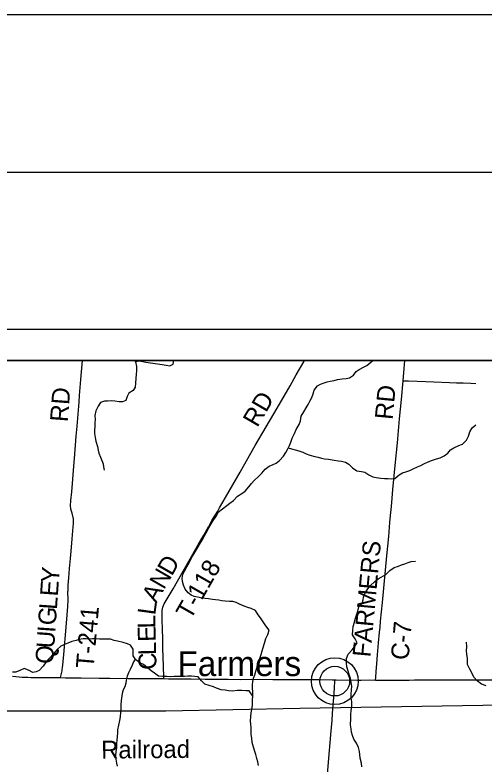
# Model space of a CAD drawing. Extents: x 0 to 48.6, y 0 to 22.
# Drawn here: x 4.141 to 5.632, y 19.616 to 22 of the extents above; entities that cross this region are included whole.
import ezdxf

# ---------------------------------------------------------------- set-up
doc = ezdxf.new("R2010")
doc.units = 0
for name, color, linetype in [('GM_X_Corporation', 7, 'Continuous'), ('GM_X_County_Road', 7, 'Continuous'), ('GM_X_County_Road_Text', 7, 'Continuous'), ('GM_X_Minor_River', 7, 'Continuous'), ('GM_X_Rail_Line', 7, 'Continuous'), ('GM_X_Rail_Line_Text', 7, 'Continuous'), ('GM_X_State_Route', 7, 'Continuous'), ('GM_X_Township_Road', 7, 'Continuous'), ('GM_X_Township_Road_Text', 7, 'Continuous'), ('GM_X_Unincorporated', 7, 'Continuous'), ('GM_X_Unincorporated_Location', 7, 'Continuous'), ('GM_X_Unincorporated_Text', 7, 'Continuous'), ('SH_Border', 7, 'Continuous'), ('SH_Cut_Line', 7, 'Continuous'), ('SH_Data', 7, 'Continuous')]:
    doc.layers.add(name, color=color, linetype=linetype)

msp = doc.modelspace()

# ---------------------------------------------------------------- linework, layer by layer
at = {"layer": 'GM_X_Corporation'}
for points in [[(8.9, 20.9), (2.1, 20.9), (2.1, 14.1)], [(5.5264, 17.0064), (5.8387, 17.2541), (6.5365, 17.7727), (6.4996, 17.9212), (6.3396, 18.6531), (6.2759, 18.9159), (6.0412, 19.8859), (5.8236, 20.7829), (5.795, 20.9), (2.1, 20.9), (2.1, 14.1)]]:
    msp.add_lwpolyline(points, dxfattribs=at)
at = {"layer": 'GM_X_County_Road'}
for points in [[(5.3742, 20.8361), (5.3776, 20.8749), (5.3801, 20.9)], [(5.2869, 19.8833), (5.2875, 19.8913), (5.2888, 19.9111), (5.2908, 19.9346), (5.2935, 19.9637), (5.2966, 20.0015), (5.2998, 20.0361), (5.301, 20.051), (5.3026, 20.0708), (5.3084, 20.1301), (5.3227, 20.2792), (5.3286, 20.3398), (5.3324, 20.385), (5.3344, 20.4073), (5.3372, 20.4357), (5.3397, 20.4623), (5.3422, 20.4895), (5.3494, 20.5662), (5.3562, 20.6386), (5.3597, 20.677), (5.3633, 20.7147), (5.3689, 20.7765), (5.3742, 20.8361)], [(5.1109, 19.3182), (5.1158, 19.3783), (5.1186, 19.4104), (5.1221, 19.4507), (5.1248, 19.4835), (5.1272, 19.5081), (5.1285, 19.523), (5.1315, 19.5583), (5.1373, 19.6214), (5.1395, 19.648), (5.143, 19.6839), (5.1452, 19.7105), (5.1471, 19.7328), (5.149, 19.755), (5.1505, 19.7774), (5.1525, 19.8046), (5.1548, 19.84), (5.1559, 19.8623), (5.1569, 19.8771), (5.1574, 19.8844)], [(5.1574, 19.8844), (5.1621, 19.8843), (5.2292, 19.8835), (5.241, 19.8835), (5.2665, 19.8836), (5.2869, 19.8833)]]:
    msp.add_lwpolyline(points, dxfattribs=at)
at = {"layer": 'GM_X_Minor_River'}
for points in [[(4.5209, 20.9), (4.5241, 20.8966), (4.5273, 20.881), (4.5267, 20.8685), (4.5254, 20.8559), (4.5245, 20.8442), (4.5239, 20.8286), (4.5226, 20.8154), (4.5164, 20.8052), (4.503, 20.7963), (4.4975, 20.7853), (4.4932, 20.7729), (4.4829, 20.7684), (4.4722, 20.7686), (4.4578, 20.7707), (4.4483, 20.7719), (4.435, 20.7713), (4.4252, 20.7711), (4.4122, 20.7663), (4.4048, 20.755), (4.3974, 20.7399), (4.3949, 20.7252), (4.3951, 20.7122), (4.395, 20.7024), (4.3945, 20.6914), (4.3935, 20.6781), (4.3938, 20.6679), (4.3955, 20.6557), (4.3976, 20.6435), (4.4031, 20.6264), (4.4052, 20.6149), (4.4077, 20.605), (4.4121, 20.5928), (4.4169, 20.5825), (4.4206, 20.5711), (4.4224, 20.5616), (4.4241, 20.5517)], [(4.5242, 20.8959), (4.5332, 20.8995), (4.5473, 20.8974), (4.5571, 20.8954), (4.5719, 20.8933), (4.5939, 20.89), (4.6087, 20.8879), (4.6212, 20.8858), (4.6329, 20.8838), (4.644, 20.889), (4.6455, 20.9)], [(5.1233, 20.8292), (5.1332, 20.8329), (5.1428, 20.835), (5.1549, 20.8368), (5.1664, 20.8397), (5.1805, 20.8425), (5.1938, 20.8431), (5.2044, 20.8456), (5.2171, 20.8542), (5.2248, 20.8655), (5.2352, 20.8722), (5.2489, 20.8792), (5.2593, 20.884), (5.2723, 20.8956), (5.2786, 20.9)], [(4.8965, 19.8323), (4.8963, 19.8456), (4.8957, 19.8577), (4.8955, 19.868), (4.8964, 19.879), (4.8992, 19.8892), (4.9028, 19.9005), (4.9063, 19.9115), (4.9107, 19.9243), (4.9135, 19.9346), (4.9175, 19.9493), (4.923, 19.9652), (4.9266, 19.9769), (4.9301, 19.9875), (4.9341, 20.0011), (4.9385, 20.0155), (4.9443, 20.0287), (4.9483, 20.0423), (4.9382, 20.0561), (4.9297, 20.0687), (4.9215, 20.0817), (4.9136, 20.0913), (4.9051, 20.1047), (4.8911, 20.111), (4.8813, 20.1138), (4.8696, 20.1185), (4.8545, 20.1247), (4.8439, 20.1302), (4.8333, 20.133), (4.8223, 20.1335), (4.8086, 20.1341), (4.7984, 20.1353), (4.7885, 20.1377), (4.7779, 20.1386), (4.7681, 20.1403), (4.7556, 20.1423), (4.7457, 20.1429), (4.7354, 20.1441), (4.7214, 20.1473), (4.7108, 20.1494), (4.701, 20.1537), (4.6909, 20.1614), (4.6815, 20.1729), (4.6764, 20.1855), (4.6731, 20.1966), (4.6721, 20.2061), (4.6742, 20.2193), (4.6792, 20.2303), (4.687, 20.2438), (4.6952, 20.2585), (4.7022, 20.2725), (4.71, 20.286), (4.7166, 20.297), (4.7232, 20.3071), (4.7306, 20.3203), (4.738, 20.332), (4.7442, 20.3448), (4.752, 20.3576), (4.7574, 20.3674), (4.7644, 20.381), (4.7706, 20.3908), (4.7803, 20.4043), (4.7866, 20.4172), (4.8004, 20.428), (4.8138, 20.4392), (4.8238, 20.4459), (4.8349, 20.4553), (4.848, 20.4687), (4.8622, 20.4769), (4.8726, 20.4844), (4.8845, 20.4983), (4.893, 20.5092), (4.9015, 20.5189), (4.9146, 20.5317), (4.9254, 20.5414), (4.9362, 20.5549), (4.9484, 20.5642), (4.9618, 20.569), (4.9714, 20.5734), (4.9817, 20.5817), (4.9944, 20.5959), (5.0014, 20.6072), (5.0069, 20.6174), (5.0128, 20.6302), (5.0178, 20.64), (5.0222, 20.6533), (5.0288, 20.6684), (5.0343, 20.6808), (5.0437, 20.6963), (5.0484, 20.7083), (5.0508, 20.7231), (5.0586, 20.7367), (5.0664, 20.7495), (5.0726, 20.7604), (5.0777, 20.7706), (5.0839, 20.7823), (5.0883, 20.794), (5.0922, 20.8061), (5.1019, 20.8196), (5.1122, 20.8256), (5.1233, 20.8292)], [(5.009, 20.622), (5.0198, 20.6195), (5.0353, 20.6147), (5.0463, 20.6123), (5.0562, 20.6088), (5.0667, 20.6037), (5.0784, 20.5986), (5.0939, 20.595), (5.1046, 20.593), (5.1148, 20.5898), (5.1246, 20.5878), (5.1368, 20.5861), (5.1549, 20.5828), (5.1686, 20.5808), (5.1781, 20.5799), (5.1909, 20.577), (5.2015, 20.5708), (5.2139, 20.5585), (5.2274, 20.5496), (5.2418, 20.5475), (5.2524, 20.5447), (5.2652, 20.537), (5.2784, 20.53), (5.289, 20.5283), (5.3031, 20.5262), (5.3156, 20.5253), (5.3266, 20.5248), (5.3387, 20.5243), (5.3486, 20.5249), (5.3617, 20.5369), (5.372, 20.5424), (5.3835, 20.5461), (5.3957, 20.5501), (5.4064, 20.5553), (5.4198, 20.5619), (5.4305, 20.5663), (5.44, 20.5712), (5.4546, 20.5778), (5.4679, 20.5829), (5.4809, 20.5873), (5.4927, 20.591), (5.5053, 20.5965), (5.5161, 20.6055), (5.5253, 20.6164), (5.5357, 20.6227), (5.5513, 20.6297), (5.5636, 20.6345), (5.5759, 20.6465), (5.5821, 20.66), (5.5865, 20.6733), (5.5935, 20.6857), (5.6054, 20.6954)], [(5.243, 19.6076), (5.242, 19.6194), (5.238, 19.635), (5.2367, 19.646), (5.2353, 19.6559), (5.2324, 19.6689), (5.2265, 19.6822), (5.2179, 19.6953), (5.2132, 19.7067), (5.2106, 19.7181), (5.2089, 19.728), (5.2075, 19.7406), (5.2078, 19.7614), (5.2087, 19.7751), (5.2093, 19.785), (5.211, 19.7997), (5.2112, 19.8138), (5.2094, 19.8271), (5.2088, 19.837), (5.2109, 19.8521), (5.211, 19.8631), (5.2097, 19.8768), (5.2068, 19.8879), (5.2032, 19.9008), (5.1995, 19.9115), (5.1952, 19.9252), (5.1946, 19.9385), (5.1948, 19.9518), (5.2003, 19.9654), (5.2126, 19.9793), (5.2196, 19.9894), (5.2285, 20.0022), (5.2218, 20.0141), (5.214, 20.0278), (5.2145, 20.0407), (5.2159, 20.0536), (5.2195, 20.0676), (5.2223, 20.0775), (5.2262, 20.0899), (5.2309, 20.1024), (5.2342, 20.116), (5.2442, 20.1269), (5.2474, 20.1383), (5.2486, 20.1477), (5.2534, 20.1613), (5.2627, 20.1737), (5.2711, 20.1839), (5.2838, 20.1962), (5.2954, 20.2056), (5.3049, 20.2108), (5.3191, 20.2197), (5.3326, 20.2324), (5.346, 20.2414), (5.3593, 20.2457), (5.3693, 20.2502), (5.3803, 20.2538), (5.3906, 20.2579), (5.4002, 20.2604), (5.4139, 20.2614)], [(4.8965, 19.8323), (4.885, 19.8488), (4.8747, 19.8493), (4.8614, 19.8502), (4.8485, 19.85), (4.8325, 19.8479), (4.8196, 19.8488), (4.8087, 19.8513), (4.7958, 19.8522), (4.7814, 19.8577), (4.7716, 19.8616), (4.7583, 19.8663), (4.7443, 19.8707), (4.7331, 19.8807), (4.7226, 19.8941), (4.7124, 19.8946), (4.7014, 19.8955), (4.6904, 19.8953), (4.6797, 19.8947), (4.6698, 19.8948), (4.6596, 19.8942), (4.6463, 19.8944), (4.6338, 19.8941), (4.6231, 19.8943), (4.6098, 19.8948), (4.5966, 19.8961), (4.5838, 19.905), (4.574, 19.9131), (4.5616, 19.9228), (4.5496, 19.9324), (4.5394, 19.9375), (4.5247, 19.9476), (4.5165, 19.9606), (4.5163, 19.9723), (4.516, 19.9822), (4.5082, 19.9941), (4.4984, 19.9988), (4.4844, 20.0031), (4.4666, 20.0068), (4.4556, 20.0088), (4.4447, 20.0131), (4.431, 20.0137), (4.4207, 20.0134), (4.4097, 20.0136), (4.3976, 20.0141), (4.3866, 20.0143), (4.3767, 20.014), (4.3668, 20.0149), (4.3573, 20.0146), (4.3451, 20.0125), (4.3352, 20.0096), (4.3215, 20.006), (4.3085, 20.0005), (4.2986, 19.9968), (4.2867, 19.9913), (4.2752, 19.9808), (4.2629, 19.9669), (4.2509, 19.9534), (4.2397, 19.941), (4.2304, 19.9275), (4.2177, 19.9136), (4.2078, 19.9092), (4.1975, 19.9078), (4.1836, 19.9148), (4.17, 19.9199), (4.1562, 19.9136), (4.1432, 19.9089), (4.1326, 19.909)], [(5.6388, 19.8648), (5.624, 19.8703), (5.6101, 19.8807), (5.5996, 19.8926), (5.593, 19.906), (5.5863, 19.9182), (5.5796, 19.9331), (5.579, 19.9426), (5.5788, 19.9529), (5.577, 19.9647), (5.5761, 19.9776), (5.5766, 19.9894), (5.5764, 20.0038)], [(4.5231, 19.9501), (4.5174, 19.9412), (4.5127, 19.9306), (4.5068, 19.9167), (4.5017, 19.9069), (4.4974, 19.8955), (4.4938, 19.8834), (4.4926, 19.874), (4.4898, 19.8622), (4.4851, 19.852), (4.4819, 19.8403), (4.4778, 19.8183), (4.4772, 19.8047), (4.4774, 19.7922), (4.4765, 19.7815), (4.4748, 19.7664), (4.4731, 19.755), (4.4695, 19.7395), (4.467, 19.7251), (4.4662, 19.7152), (4.4653, 19.7042), (4.4643, 19.6921), (4.4638, 19.6811), (4.4629, 19.6686), (4.4612, 19.655), (4.4603, 19.6428), (4.4609, 19.6314), (4.463, 19.6192), (4.4655, 19.6097)], [(4.9153, 19.6119), (4.9124, 19.6233), (4.9098, 19.6336), (4.9058, 19.6462), (4.9029, 19.6564), (4.8993, 19.6698), (4.8946, 19.6843), (4.8932, 19.6987), (4.8919, 19.7097), (4.8913, 19.7215), (4.891, 19.7321), (4.89, 19.7428), (4.889, 19.753), (4.89, 19.7678), (4.8913, 19.7796), (4.8937, 19.7902), (4.8961, 19.8034), (4.896, 19.8201), (4.8965, 19.8323)]]:
    msp.add_lwpolyline(points, dxfattribs=at)
at = {"layer": 'GM_X_Rail_Line'}
msp.add_lwpolyline([(2.1, 19.7643), (2.1011, 19.7645), (2.172, 19.7738), (2.2311, 19.7779), (2.3038, 19.7803), (2.4027, 19.7791), (2.7583, 19.782), (3.4579, 19.785), (4.2295, 19.785), (4.6206, 19.7852), (5.0462, 19.7937), (5.6922, 19.8043), (6.0216, 19.8102), (6.7352, 19.82), (7.2096, 19.8291), (8.1004, 19.8459), (8.9, 19.8619)], dxfattribs=at)
at = {"layer": 'GM_X_State_Route'}
for points in [[(4.1327, 19.8955), (4.1538, 19.8938), (4.164, 19.8931), (4.1736, 19.8925), (4.1819, 19.8923), (4.191, 19.892), (4.2018, 19.8918), (4.2333, 19.8914), (4.2675, 19.8913), (4.2852, 19.8911), (4.3016, 19.8909), (4.3507, 19.8904), (4.4085, 19.8899), (4.442, 19.8896), (4.4998, 19.8888), (4.5038, 19.8887)], [(4.5038, 19.8887), (4.539, 19.8883), (4.5881, 19.8882), (4.614, 19.8879), (4.6291, 19.8878), (4.6533, 19.8877), (4.7005, 19.8871), (4.7452, 19.8865), (4.7726, 19.8865), (4.7993, 19.8859), (4.8179, 19.8858), (4.8583, 19.8857), (4.8937, 19.8858), (4.9608, 19.8855), (4.9851, 19.8856), (5.0435, 19.8853), (5.0689, 19.8853), (5.1068, 19.8849), (5.1497, 19.8846), (5.1574, 19.8844)], [(5.1574, 19.8844), (5.1621, 19.8843), (5.2292, 19.8835), (5.241, 19.8835), (5.2665, 19.8836), (5.2869, 19.8833)], [(5.2869, 19.8833), (5.2882, 19.8833), (5.3031, 19.8833)], [(5.3031, 19.8833), (5.3379, 19.8833), (5.3653, 19.8834), (5.3814, 19.8834), (5.3939, 19.8835), (5.4106, 19.8838), (5.4417, 19.8836), (5.469, 19.8838), (5.5206, 19.8841), (5.5529, 19.8841), (5.5945, 19.8845), (5.6016, 19.8845)], [(5.6016, 19.8845), (5.6585, 19.8846), (5.693, 19.8845), (5.7225, 19.8845), (5.7909, 19.8848), (5.8275, 19.8848), (5.866, 19.8849), (5.8853, 19.8848), (5.9437, 19.8851), (6.0015, 19.8853), (6.0414, 19.8854)]]:
    msp.add_lwpolyline(points, dxfattribs=at)
at = {"layer": 'GM_X_Township_Road'}
for points in [[(4.2852, 19.8911), (4.2873, 19.8998), (4.2895, 19.9089), (4.2902, 19.913), (4.2909, 19.9168), (4.2916, 19.9229), (4.2927, 19.931), (4.2949, 19.9545), (4.2959, 19.9638), (4.2979, 19.9904), (4.3011, 20.0263), (4.3068, 20.0912), (4.3089, 20.1179), (4.3092, 20.1248), (4.3095, 20.1309), (4.3096, 20.135), (4.3096, 20.1384), (4.3094, 20.144), (4.3093, 20.1495), (4.3092, 20.1542), (4.3091, 20.1582), (4.3091, 20.1615), (4.3091, 20.1651), (4.3093, 20.1689), (4.3094, 20.1719), (4.3103, 20.1855), (4.3122, 20.2091), (4.3144, 20.2388), (4.317, 20.2704), (4.3189, 20.2933), (4.3223, 20.3329), (4.326, 20.3706), (4.3268, 20.3812), (4.3268, 20.3848), (4.3268, 20.3892), (4.3265, 20.3935), (4.3262, 20.3973), (4.3255, 20.4011), (4.3247, 20.4052), (4.322, 20.4148), (4.3202, 20.4208), (4.3195, 20.4241), (4.3187, 20.4274), (4.3182, 20.431), (4.3177, 20.4354), (4.3176, 20.4397), (4.3176, 20.4435), (4.318, 20.4498), (4.3183, 20.4546), (4.3209, 20.4825), (4.3233, 20.5091), (4.3276, 20.5642), (4.3296, 20.589), (4.3354, 20.6596), (4.338, 20.6918), (4.3401, 20.7171), (4.3443, 20.7673), (4.3461, 20.789), (4.35, 20.8398), (4.3551, 20.9)], [(4.614, 19.8879), (4.6138, 19.8957), (4.6133, 19.9249), (4.6119, 19.9597), (4.6112, 19.982), (4.6105, 20.0087), (4.6093, 20.0516), (4.6088, 20.0683), (4.6081, 20.0981), (4.6084, 20.1043), (4.6092, 20.1099), (4.6106, 20.1153), (4.6126, 20.1205), (4.6151, 20.1255), (4.6278, 20.1476), (4.6432, 20.1739), (4.6938, 20.2615), (4.7242, 20.3157), (4.7409, 20.3448), (4.7573, 20.3733), (4.7585, 20.3755), (4.7667, 20.3908), (4.7721, 20.3999), (4.778, 20.4094), (4.785, 20.4212), (4.7909, 20.4313), (4.8212, 20.4841), (4.856, 20.5451), (4.8672, 20.5645), (4.8907, 20.6054), (4.9047, 20.6296), (4.9392, 20.6893), (4.9631, 20.7307), (4.9961, 20.7869), (5.015, 20.8198), (5.0348, 20.8543), (5.0589, 20.8963), (5.061, 20.9)], [(5.3742, 20.8361), (5.3912, 20.8352), (5.4471, 20.8335), (5.4719, 20.8323), (5.5222, 20.8304), (5.5439, 20.8297), (5.5657, 20.8288), (5.5893, 20.8279), (5.6054, 20.8271)]]:
    msp.add_lwpolyline(points, dxfattribs=at)
at = {"layer": 'GM_X_Unincorporated'}
for radius in [0.0744, 0.0472]:
    msp.add_circle((5.1573, 19.8799), radius, dxfattribs=at)
at = {"layer": 'GM_X_Unincorporated_Location'}
msp.add_line((5.1573, 19.8799), (5.1573, 19.8799), dxfattribs=at)
at = {"layer": 'SH_Border'}
msp.add_lwpolyline([(1.5, 21.5), (33.5, 21.5), (33.5, 0.5), (1.5, 0.5)], close=True, dxfattribs=at)
at = {"layer": 'SH_Cut_Line'}
msp.add_lwpolyline([(0, 0), (34, 0), (34, 22), (0, 22)], close=True, dxfattribs=at)
at = {"layer": 'SH_Data'}
for p, q in [((2, 21), (9, 21)), ((2.1, 20.9), (8.9, 20.9))]:
    msp.add_line(p, q, dxfattribs=at)

# ---------------------------------------------------------------- texts
at = {"layer": 'GM_X_County_Road_Text'}
for s, rotation, p in [('RD', 84.5776, (5.3409, 20.7104)), ('FARMERS', 84.7126, (5.2701, 19.9547)), ('C-7', 84.9859, (5.3916, 19.9456))]:
    msp.add_text(s, height=0.05682, rotation=rotation, dxfattribs=at).set_placement(p)
at = {"layer": 'GM_X_Rail_Line_Text'}
msp.add_text('Railroad', height=0.05663, rotation=0.4496, dxfattribs=at).set_placement((4.415, 19.6335))
at = {"layer": 'GM_X_Township_Road_Text'}
for s, height, rotation, p in [('RD', 0.05682, 85.5983, (4.3085, 20.7034)), ('RD', 0.05682, 59.7136, (4.911, 20.685)), ('D', 0.0568, 59.994, (4.6392, 20.2121)), ('T-118', 0.05682, 60.1879, (4.6985, 20.0725)), ('Y', 0.0568, 85.6463, (4.2797, 20.1908)), ('N', 0.0568, 59.994, (4.6142, 20.1688)), ('E', 0.0568, 85.9724, (4.2768, 20.1485)), ('A', 0.0568, 61.2596, (4.5903, 20.1253)), ('L', 0.0568, 85.9905, (4.2738, 20.1061)), ('L', 0.0568, 82.1978, (4.5863, 20.0884)), ('G', 0.0568, 85.9877, (4.2703, 20.0562)), ('T-241', 0.05682, 85.0057, (4.3906, 19.9187)), ('L', 0.0568, 91.3672, (4.5874, 20.0483)), ('I', 0.0568, 85.9845, (4.2687, 20.033)), ('E', 0.0568, 91.5153, (4.5885, 20.0058)), ('U', 0.0568, 85.986, (4.2652, 19.9831)), ('L', 0.0568, 91.5113, (4.5896, 19.9633)), ('Q', 0.0568, 85.986, (4.2617, 19.9332)), ('C', 0.0568, 91.5067, (4.5909, 19.9167))]:
    msp.add_text(s, height=height, rotation=rotation, dxfattribs=at).set_placement(p)
at = {"layer": 'GM_X_Unincorporated_Text'}
msp.add_text('Farmers', height=0.07898, rotation=0, dxfattribs=at).set_placement((4.6574, 19.8961))

doc.saveas('drawing.dxf')
